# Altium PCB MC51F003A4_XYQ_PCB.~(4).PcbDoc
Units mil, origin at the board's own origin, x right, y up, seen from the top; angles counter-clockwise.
Board outline 2175.03 x 1405.03 mil, 2 copper layers (Top Layer, Bottom Layer); 32 components, 23 nets, 110 pads, 48 vias.
Unrouted connection lines stored in the file: 46.
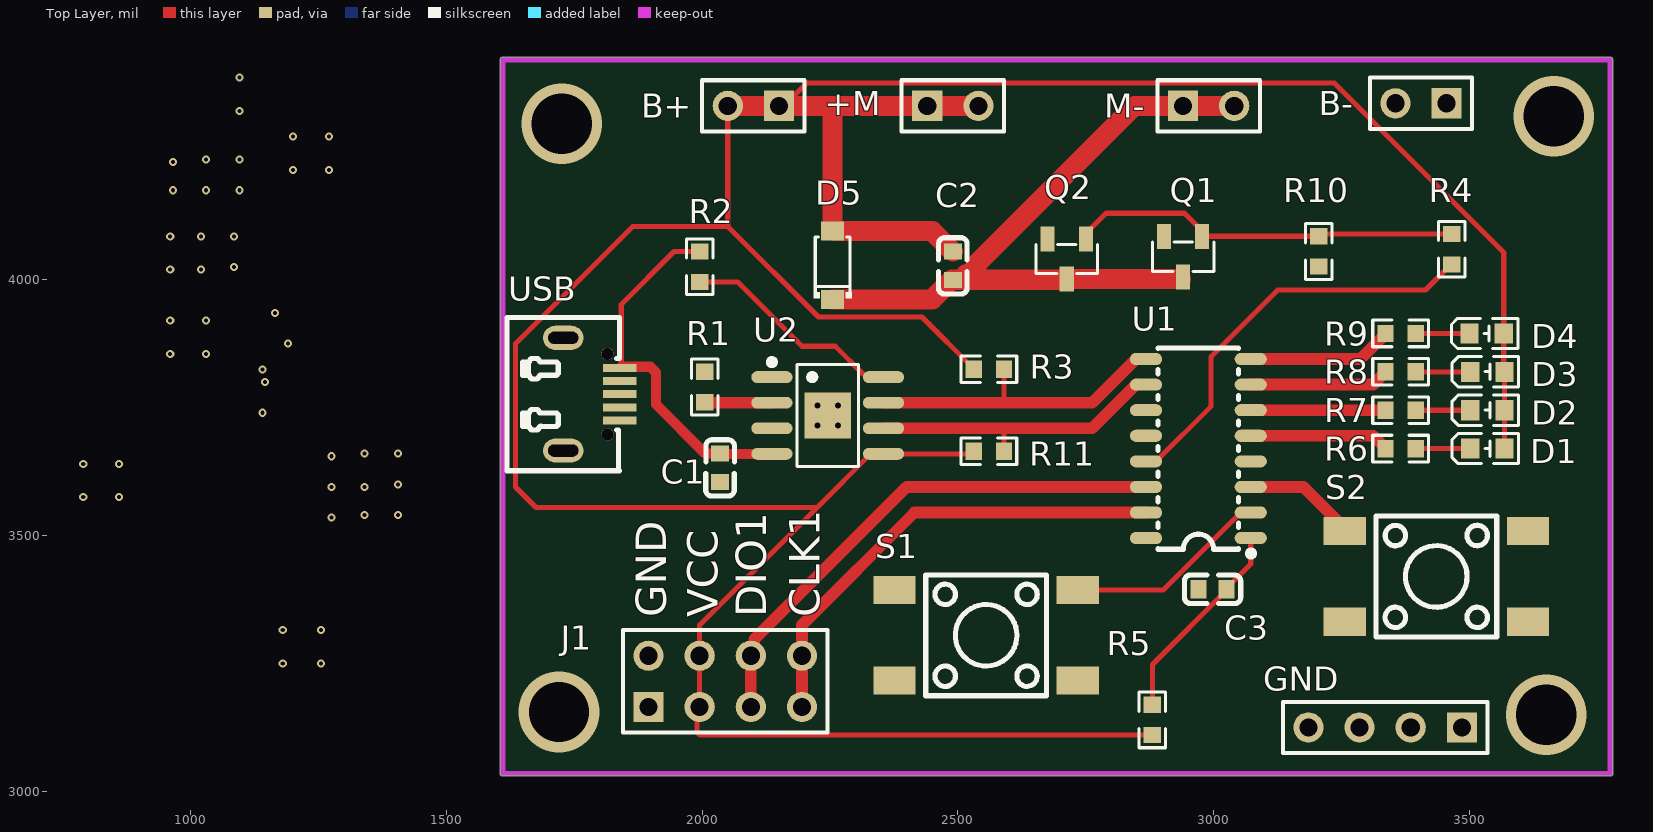
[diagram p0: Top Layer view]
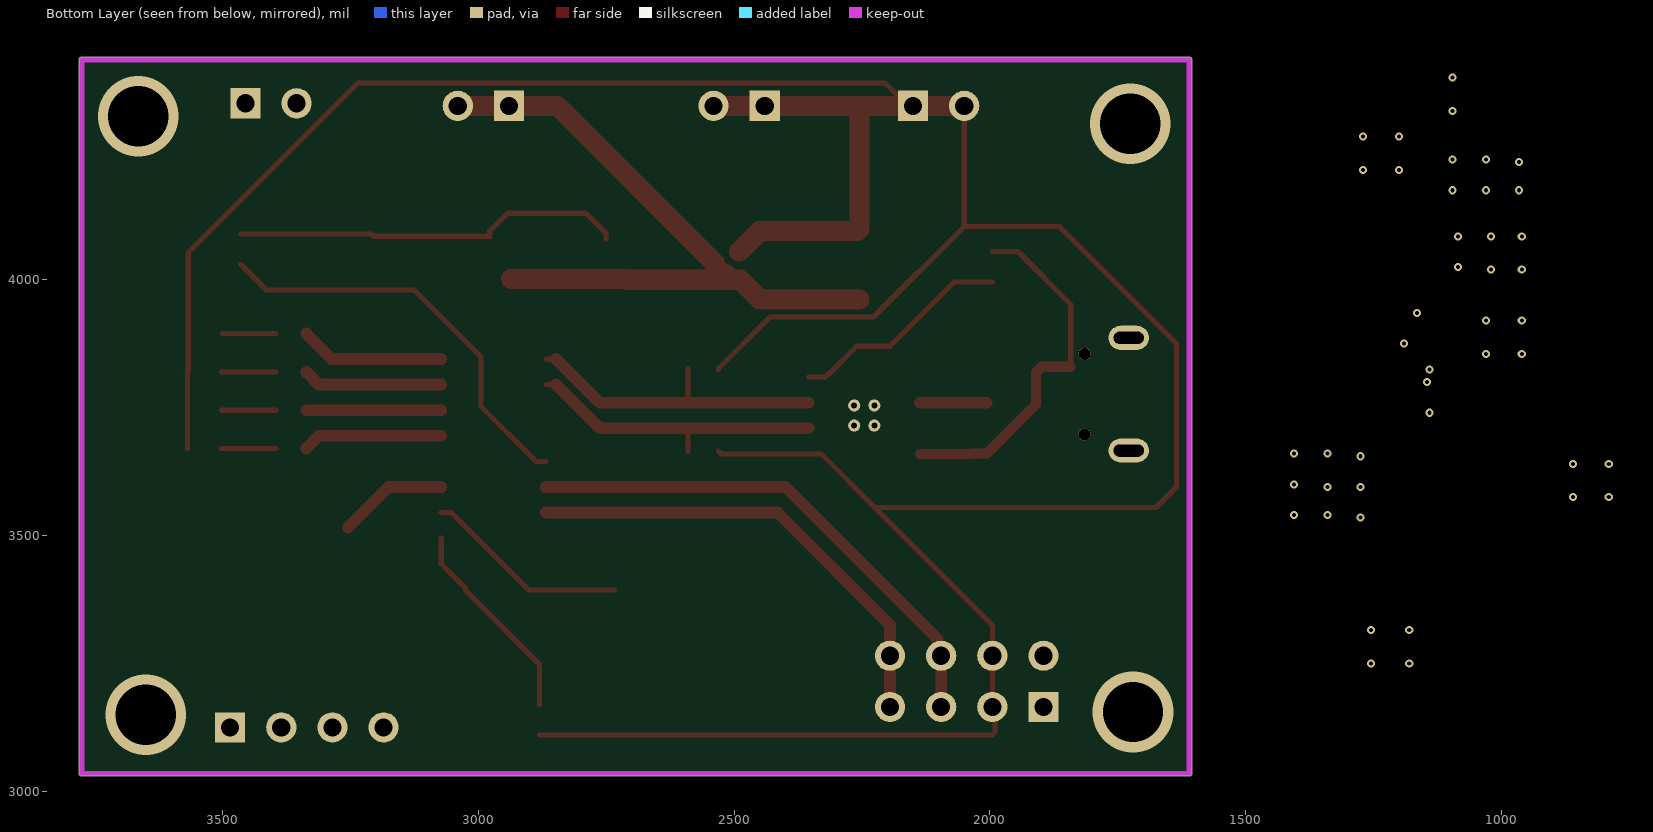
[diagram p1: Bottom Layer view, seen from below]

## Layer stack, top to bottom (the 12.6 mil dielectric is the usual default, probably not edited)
Top Solder: solder mask 0.4, Solder Resist, Dk 3.5
Top Layer: signal copper 1.4
Dielectric 1: dielectric 12.6, FR-4, Dk 4.8
Bottom Layer: signal copper 1.4
Bottom Solder: solder mask 0.4, Solder Resist, Dk 3.5

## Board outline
1610,3029.99 cw(c1610,3035) 1604.98,3035 1604.98,4430 cw(c1610,4430) 1610,4435.02 3775,4435.02 cw(c3775,4430) 3780.01,4430 3780.01,3035 cw(c3775,3035) 3775,3029.99

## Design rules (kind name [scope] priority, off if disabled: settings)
Clearance [All] p1: gap=10 ignorepadtopadclearanceinfootprint=FALSE
PolygonConnect [All] p1: connectstyle=Relief reliefconductorwidth=10 reliefentries=4 polygonreliefangle="90 Angle" airgapwidth=10
RoutingVias [All] p1: holewidth=28 width=50 viastyle="Through Hole" minholewidth=28 minwidth=50 maxholewidth=28 maxwidth=50
SilkToSolderMaskClearance [IsPad] p1: minsilkscreentomaskgap=0 clearancetoexposedcopper=TRUE
SolderMaskExpansion [All] p1: expansion=4 istentingtop=FALSE
Width [All] p1: maxlimit=157.48 minlimit=10 preferedwidth=12
29 further rules are at their usual default settings.

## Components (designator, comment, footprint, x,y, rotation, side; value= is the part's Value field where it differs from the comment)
B+ "MHDR1X2" HDR1X2 2150,4340 r180 top
B- "MHDR1X2" HDR1X2 3455,4345 r180 top
C1 "Cap" C0603 2035,3632.45 r90 top value=10uF
C2 "Cap" C0603 2490,4027.45 r90 top value=100nF
C3 "Cap" C0603 2997.45,3395 r180 top value=0.1uF
D1 "LED0" LED0603-FD 3535,3670 r180 top
D2 "LED0" LED0603-FD 3535,3745 r180 top
D3 "LED0" LED0603-FD 3535,3820 r180 top
D4 "LED0" LED0603-FD 3533.47,3895 r180 top
D5 "Diode" SOD-123_L2.8-W1.8-LS3.7-RD 2255,4028.37 r90 top
GND "MHDR1X4" HDR1X4 3485,3125 r180 top
J1 "Header 4X2" HDR2X4 1895,3165 r0 top
M+ "Header 2" HDR1X2 2440,4340 r0 top
M- "Header 2" HDR1X2 2940,4340 r0 top
Q1 "NMOS-2" SOT-23-3_L2.9-W1.3-P1.90-LS2.4-BR 2940,4045 r90 top
Q2 "NMOS-2" SOT-23-3_L2.9-W1.3-P1.90-LS2.4-BR 2712.6,4040.63 r90 top
R1 "Res2" R0603 2005,3790.34 r270 top value=5.1K
R2 "Res2" R0603 1995,4025.35 r90 top value=1K
R3 "Res2" R0603 2560.34,3825 r180 top value=1K
R4 "Res2" R0603 3465,4059.66 r90 top value=1K
R5 "Res2" R0603 2880,3139.66 r90 top value=5R
R6 "Res2" R0603 3365.34,3670 r180 top value=510
R7 "Res2" R0603 3365.34,3745 r180 top value=510
R8 "Res2" R0603 3365.34,3820 r180 top value=510
R9 "Res2" R0603 3365.35,3895 r0 top value=510
R10 "Res2" R0603 3205,4055.35 r90 top value=100K
R11 "Res2" R0603 2560.35,3665 r0 top value=1K
S1 "SW-PB" SW-SMD_4P-L6.0-W6.0-P4.50-LS10.0_UK-B0228XXX 2555,3305 r180 top
S2 "SW-PB" SW-SMD_4P-L6.0-W6.0-P4.50-LS10.0_UK-B0228XXX 3435,3420 r0 top
U1 "MC51F003A4_SOP16" SOP-16_L9.9-W3.9-P1.27-LS6.1-BL 2970,3670 r90 top
U2 "TC4056" SOP-8_L4.9-W3.9-P1.27-LS6.0-BL-EP 2245.32,3734.69 r270 top
USB "MHDR1X5" MICRO-USB-SMD_MICRO-USB-A12 1783.49,3776.3 r270 top

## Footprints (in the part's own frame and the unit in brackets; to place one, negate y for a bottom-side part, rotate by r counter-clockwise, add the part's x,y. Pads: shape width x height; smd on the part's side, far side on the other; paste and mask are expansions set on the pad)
C0603 [mm]
  rect 0.8x0.9 smd: 1(-0.7,0) 2(0.7,0)
  silkscreen extent -1.41,-0.71 1.39,0.72
HDR1X2 [mm] "Connector; Header; 2 Position"
  rect 1.5x1.5 hole 0.9: 1(0,0)
  round 1.5 hole 0.9: 2(2.54,0)
  silkscreen extent -1.27,-1.27 3.81,1.27
HDR1X4 [mm] "Connector; Header; 4 Position"
  rect 1.5x1.5 hole 0.9: 1(0,0)
  round 1.5 hole 0.9: 2(2.54,0) 3(5.08,0) 4(7.62,0)
  silkscreen extent -1.27,-1.27 8.89,1.27
HDR2X4 [mm] "Connector; Header; 4x2 Position"
  rect 1.5x1.5 hole 0.9: 1(0,0)
  round 1.5 hole 0.9: 2(0,2.54) 3(2.54,0) 4(2.54,2.54) 5(5.08,0) 6(5.08,2.54) 7(7.62,0) 8(7.62,2.54)
  silkscreen extent -1.27,-1.27 8.89,3.81
LED0603-FD [mm]
  rect 0.9x1 smd: 1(-0.85,0) 2(0.85,0)
  silkscreen extent -1.55,-0.75 1.75,0.75
MICRO-USB-SMD_MICRO-USB-A12 [mm]
  rect 0.4x1.65 smd: 1(-1.3,1.4) 2(-0.65,1.4) 3(0,1.4) 4(0.65,1.4) 5(1.3,1.4)
  oval 1.2x2 hole 0.6 slot 1.5 at 90 deg: 6(2.799,-1.4) 7(-2.799,-1.4)
  round 0.6 hole 0.6 unplated: ""(-1.999,0.8) ""(1.999,0.8)
  silkscreen extent -3.8,-4.2 3.8,1.4
R0603 [mil]
  rect 31.75x34.02 smd: 1(-29.66,0) 2(29.65,0)
  silkscreen extent -55,-26 55,26
SOD-123_L2.8-W1.8-LS3.7-RD [mm]
  rect 0.95x1.15 smd: 1(-1.693,0) 2(1.693,0)
  silkscreen extent -1.63,-0.94 1.41,0.94
SOP-8_L4.9-W3.9-P1.27-LS6.0-BL-EP [mm]
  oval 0.588x2.045 smd: 1(-1.905,-2.773) 2(-0.635,-2.773) 3(0.635,-2.773) 4(1.905,-2.773) 5(1.905,2.773) 6(0.635,2.773) 7(-0.635,2.773) 8(-1.905,2.773)
  round 0.6 hole 0.3: 9(-0.5,0.5) 9(-0.5,-0.5) 9(0.5,0.5) 9(0.5,-0.5)
  rect 2.29x2.29 smd: 9(0,0)
  silkscreen extent -2.8,-2.92 2.53,1.52
SOP-16_L9.9-W3.9-P1.27-LS6.1-BL [mm]
  oval 0.6x1.6 smd: 1(-4.445,-2.6) 2(-3.175,-2.6) 3(-1.905,-2.6) 4(-0.635,-2.6) 5(0.635,-2.6) 6(1.905,-2.6) 7(3.175,-2.6) 8(4.445,-2.6) 9(4.445,2.6) 10(3.175,2.6) 11(1.905,2.6) 12(0.635,2.6) 13(-0.635,2.6) 14(-1.905,2.6) 15(-3.175,2.6) 16(-4.445,2.6)
  silkscreen extent -5.36,-2.76 5,2
SOT-23-3_L2.9-W1.3-P1.90-LS2.4-BR [mm]
  rect 1.25x0.7 smd: 1(1,-0.95) 2(1,0.95) 3(-1,0)
  silkscreen extent -0.73,-1.53 0.73,1.53
SW-SMD_4P-L6.0-W6.0-P4.50-LS10.0_UK-B0228XXX [mm]
  rect 2.1x1.4 smd: 1(-4.55,2.25) 2(4.55,2.25) 3(-4.55,-2.25) 4(4.55,-2.25)
  silkscreen extent -3,-3 3,3

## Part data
B+ B- M+ M-: "Header, 2-Pin"
C1 C2 C3: "Capacitor"
D1 D2 D3 D4: "Typical INFRARED GaAs LED"
D5: "Default Diode"
GND: "Header, 4-Pin"
J1: "Header, 4-Pin, Dual row"
Q1 Q2: "N-Channel Power MOSFET"
R1 R2 R3 R4 R5 R6 R7 R8 R9 R10 R11: "Resistor"
S1 S2: "Switch"
USB: "Header, 5-Pin"

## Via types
v1: diameter 15.75, hole 7.87, Top Layer to Bottom Layer, 44 vias
v2: diameter 157.48, hole 118.11, Top Layer to Bottom Layer, 4 vias

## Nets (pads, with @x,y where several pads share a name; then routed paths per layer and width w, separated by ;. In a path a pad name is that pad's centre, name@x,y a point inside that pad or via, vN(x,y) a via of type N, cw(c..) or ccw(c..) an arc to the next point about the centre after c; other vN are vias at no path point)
B+: B+.1 B+.2 C2.2 D1.1 D2.1 D3.1 D4.1 D5.2 J1.3 J1.4 M+.1 M+.2 R3.2 R5.1 R11.1 U2.5 | length 6940
  Top Layer w10: B+.2 2050,4104.18 ; B+.1@2160,4340 2204.53,4384.53 3235.47,4384.53 3566.93,4053.07 3566.93,3821.53 D3.1 D2.1 D1.1 ; D5.2@2255,4098.94 D5.2@2258.94,4095 ; R11.1 2525.38,3659.69 U2.5 2329.35,3659.69 2224.66,3555 ; R3.2 2530.69,3826.13 2429.78,3927.05 2227.13,3927.05 2050,4104.18 ; R5.1 1995.86,3110 1990,3115.86 1990,3160 J1.3 J1.4 1995,3325.34 2224.66,3555 ; 2050,4104.18 1864.18,4104.18 1635,3875 1635,3595 1675,3555 2224.66,3555
  Top Layer w39.37: B+.2 B+.1 2160,4340 2255,4340 ; D5.2@2255,4098.94 2255,4340 ; D5.2@2258.94,4095 2450,4095 C2.2 ; M+.2 M+.1 2255,4340
BAT_F_IN: R3.1 U1.9 U2.7 | length 613.8
  Top Layer w10: 2590,3759.69 R3.1 ; U1.9@2847.95,3845 U1.9
  Top Layer w23: U2.7 2590,3759.69 2762.64,3759.69 U1.9@2847.95,3845
BAT_FINISH_IN: R11.2 U1.10 U2.6 | length 593.2
  Top Layer w10: R11.2 2590,3709.69 ; U1.10@2847.95,3795 U1.10
  Top Layer w23: U2.6 2590,3709.69 2762.64,3709.69 U1.10@2847.95,3795
CLK1: J1.7 J1.8 U1.15 | length 923.8
  Top Layer w23: J1.7 2195,3325 2415,3545 U1.15
DIO1: J1.5 J1.6 U1.14 | length 1024
  Top Layer w23: J1.5 J1.6 2101.9,3271.9 2101.9,3296.9 2400,3595 U1.14
GND: B-.1 B-.2 C1.1 C3.2 GND.1 GND.2 GND.3 GND.4 J1.1 J1.2 Q1.2 Q2.2 R1.1 R10.1 S1.2 S2.4 U1.16 U2.1 U2.3 USB.5
  other v1: 1180,3250 1255,3250 1180,3315 1255,3315 1275,3535 1340,3540 1405,3540 790,3575 860,3575 1275,3595 1340,3595 1405,3600 790,3640 860,3640 1275,3655 1340,3660 1405,3660 1140,3740 1145,3800 1140,3825 960,3855 1030,3855 1190,3875 960,3920 1030,3920 1165,3935 960,4020 1020,4020 1085,4025 960,4085 1020,4085 1085,4085 965,4175 1030,4175 1095,4175 1200,4215 1270,4215 965,4230 1030,4235 1095,4235 1200,4280 1270,4280 1095,4330 1095,4395
LED1: R6.2 U1.5 | length 274.3
  Top Layer w23: U1.5 3311.82,3695 3335.69,3671.13 R6.2
LED2: R7.2 U1.6 | length 263.3
  Top Layer w23: U1.6 R7.2
LED3: R8.2 U1.7 | length 274.3
  Top Layer w23: U1.7 3311.83,3795 3335.69,3818.87 R8.2
LED4: R9.1 U1.8 | length 284.7
  Top Layer w23: U1.8 3286.83,3845 3335.69,3893.87 R9.1
M_IN: R4.1 U1.13 | length 813.8
  Top Layer w10: U1.13 2887.32,3645 2994.96,3752.65 2994.96,3849.96 3125,3980 3413.87,3980 3463.87,4030 R4.1
NetC2_1: C2.1 D5.1 M-.1 M-.2 Q1.3 Q2.3 | length 1408.1
  Top Layer w10: C2.1 2500.75,4010.64 2525.64,4010.64 ; Q1.3@2935.63,4001.26 Q1.3
  Top Layer w39.37: D5.1 2449.87,3961.73 2488.03,3999.89 C2.1 2525.64,3999.89 2711.22,3999.89 Q2.3 Q1.3@2935.63,4001.26 ; 2515.64,4010.64 2516.71,4009.57 2520.01,4009.57 2537.4,4026.96 2537.4,4032.4 2845,4340 M-.1 M-.2
NetC3_1: C3.1 R5.2 U1.1 | length 405.4
  Top Layer w10: R5.2 2880,3248.03 3025,3393.03 C3.1 3025,3396.97 3072.37,3444.33 U1.1
NetD1_2: D1.2 R6.1 | length 106.5
  Top Layer w10: R6.1 D1.2
NetD2_2: D2.2 R7.1 | length 106.5
  Top Layer w10: R7.1 D2.2
NetD3_2: D3.2 R8.1 | length 106.5
  Top Layer w10: R8.1 D3.2
NetD4_2: D4.2 R9.2 | length 105
  Top Layer w10: R9.2 D4.2
NetQ1_1: Q1.1 Q2.1 R4.2 R10.2 | length 769.3
  Top Layer w10: Q2.1 2750,4090.83 2789.17,4130 2942.6,4130 2977.4,4095.2 Q1.1 2978.03,4085 R10.2 3209.31,4089.31 R4.2
NetR1_2: R1.2 U2.2 | length 131.6
  Top Layer w10: R1.2 R1.2@2006,3759.69
  Top Layer w23: R1.2@2006,3759.69 U2.2
NetR2_1: R2.1 U2.8 | length 436.5
  Top Layer w10: R2.1 2069.31,3995.69 2195,3870 2260,3870 2314.26,3815.74 2316.18,3815.74 2322.23,3809.69 U2.8
NetS1_3: S1.3 U1.2 | length 401
  Top Layer w10: S1.3 2901.26,3393.58 3052.68,3545 U1.2
NetS2_1: S2.1 U1.3 | length 215.8
  Top Layer w23: U1.3 3175,3595 S2.1@3255,3515
P+: C1.2 R2.2 U2.4 USB.1 | length 726.4
  Top Layer w10: USB.1 USB.1@1841.1,3825 ; USB.1@1838.94,3827.5 1841.81,3830.37 1841.81,3951.81 1945,4055 R2.2 ; C1.2 C1.2@2035.31,3659.69
  Top Layer w19.68: USB.1@1841.81,3830 1898.47,3830 1910,3818.47 1910,3756.1 2006.1,3660 C1.2 ; C1.2@2035.31,3659.69 U2.4
pads on no net: S1.1 S1.4 S2.2 S2.3 U1.4 U1.11 U1.12 U2.9 USB. USB.2 USB.3 USB.4 USB.6 USB.7
copper on no net:
  other v2: 3650,3150 1720,3155 1725,4305 3665,4320

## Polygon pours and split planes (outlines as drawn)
GND on Top Layer "NONET_L01_P018" (solid, shelved, pour order 18): 1610.85,4429.47 1610.85,3035.85 1610,3035 3775,3035 3775,4430
GND on Top Layer "NONET_L01_P016" (solid, shelved, pour order 16): 1610,4430 1610,3035 3775,3035 3775,4430
GND on Top Layer "NONET_L01_P001" (solid, shelved, pour order 1): 2935,3655
GND on Bottom Layer "NONET_L02_P019" (solid, shelved, pour order 19): 1610,4430 1610,3035 3775,3035 3775,4430
GND on Bottom Layer "NONET_L02_P015" (solid, shelved, pour order 15): 1610,4430 1610,3035 3775,3035 3775,4430

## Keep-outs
Keep-Out Layer:
  lines w10: 1610,3035 1610,4430 3775,4430 3775,3035 1610,3035

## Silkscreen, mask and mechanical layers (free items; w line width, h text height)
Top Overlay:
  text "GND" at 1930,3340 h60 r90
  text "VCC" at 2030,3340 h60 r90
  text "DIO1" at 2125,3340 h60 r90
  text "CLK1" at 2230,3340 h60 r90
